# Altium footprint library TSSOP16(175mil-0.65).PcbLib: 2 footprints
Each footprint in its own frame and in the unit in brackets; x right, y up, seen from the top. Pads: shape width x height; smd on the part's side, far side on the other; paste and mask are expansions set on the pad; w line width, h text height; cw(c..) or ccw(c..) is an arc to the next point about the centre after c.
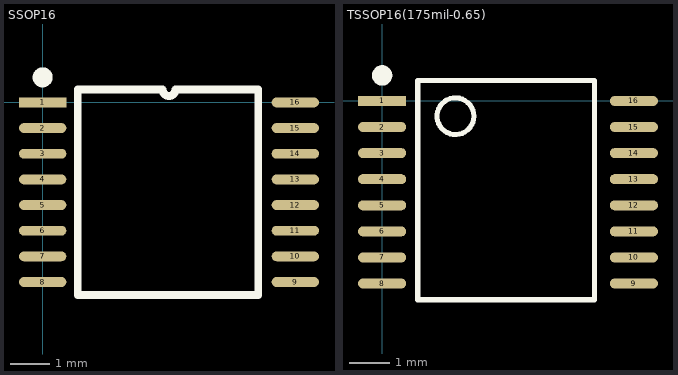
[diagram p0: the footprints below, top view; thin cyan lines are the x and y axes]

## SSOP16 [mm]
pads (16):
  rect 1.2x0.25 smd: 1(0,0)
  oval 1.2x0.25 smd: 2(0,-0.65) 3(0,-1.3) 4(0,-1.95) 5(0,-2.6) 6(0,-3.25) 7(0,-3.9) 8(0,-4.55) 9(6.4,-4.55) 10(6.4,-3.9) 11(6.4,-3.25) 12(6.4,-2.6) 13(6.4,-1.95) 14(6.4,-1.3) 15(6.4,-0.65) 16(6.4,0)
Top Overlay:
  circle w0.254: c0,0.635 r0.127
  lines w0.2: 0.889,-4.875 5.461,-4.875 5.461,0.325 3.362,0.325 cw(c3.2,0.325) 3.037,0.325 0.889,0.325 0.889,-4.875

## TSSOP16(175mil-0.65) [mm]
pads (16):
  rect 1.2x0.25 smd: 1(0,0)
  oval 1.2x0.25 smd: 2(0,-0.65) 3(0,-1.3) 4(0,-1.95) 5(0,-2.6) 6(0,-3.25) 7(0,-3.9) 8(0,-4.55) 9(6.273,-4.55) 10(6.273,-3.9) 11(6.273,-3.25) 12(6.273,-2.6) 13(6.273,-1.95) 14(6.273,-1.3) 15(6.273,-0.65) 16(6.273,0)
Top Overlay:
  circle w0.254: c0,0.635 r0.127
  circle w0.127: c1.828,-0.381 r0.458
  lines w0.127: 0.889,-4.953 0.889,0.508 5.289,0.508 5.289,-4.953 0.889,-4.953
